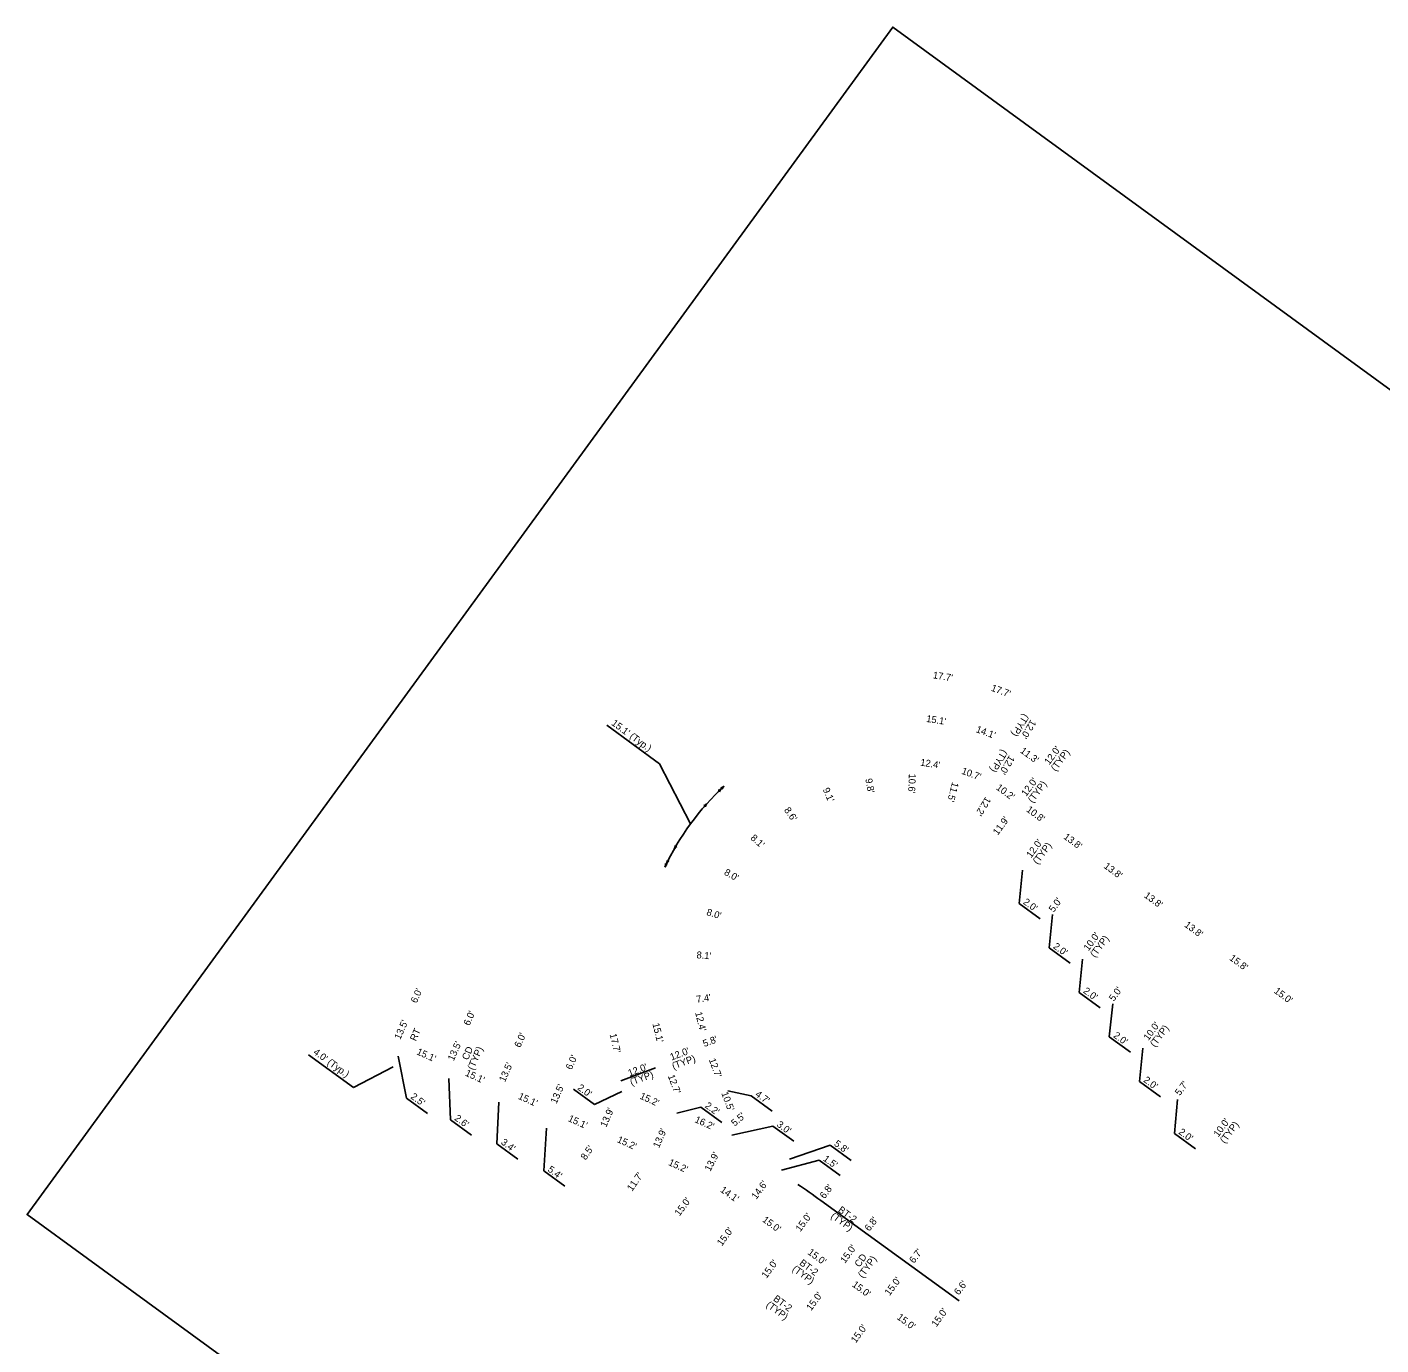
# Model space of a CAD drawing. Extents: x 15567221 to 15568484, y 8782768 to 8783889.
# Drawn here: x 15567746.9 to 15568115.4, y 8783249.6 to 8783608.3 of the extents above; entities that cross this region are included whole.
import ezdxf

# ---------------------------------------------------------------- set-up
doc = ezdxf.new("R2010")
doc.units = 0
for name, color, linetype in [('Drainage', 7, 'Continuous'), ('EXT_C', 7, 'Continuous'), ('EXT_GU', 7, 'Continuous'), ('NamedBoundary', 7, 'Continuous'), ('SheetText', 7, 'Continuous')]:
    doc.layers.add(name, color=color, linetype=linetype)

msp = doc.modelspace()

# ---------------------------------------------------------------- linework, layer by layer
at = {"layer": 'Drainage'}
for p, q in [((15567904.72, 8783418.28), (15567919.08, 8783407.82)), ((15567927.51, 8783391.49), (15567919.08, 8783407.82)), ((15568017.87, 8783378.83), (15568016.94, 8783369.8)), ((15568022.66, 8783365.63), (15568016.94, 8783369.8)), ((15568026.05, 8783366.75), (15568025.13, 8783357.72)), ((15568030.85, 8783353.55), (15568025.13, 8783357.72)), ((15568034.24, 8783354.63), (15568033.32, 8783345.6)), ((15568039.04, 8783341.43), (15568033.32, 8783345.6)), ((15568042.43, 8783342.5), (15568041.51, 8783333.47)), ((15568047.23, 8783329.3), (15568041.51, 8783333.47)), ((15567835.75, 8783319.69), (15567823.53, 8783328.6)), ((15567847.89, 8783328.25), (15567850.22, 8783316.84)), ((15568050.63, 8783330.38), (15568049.7, 8783321.35)), ((15567846.6, 8783325.3), (15567835.75, 8783319.69)), ((15567861.74, 8783322.19), (15567862.16, 8783310.95)), ((15568055.42, 8783317.18), (15568049.7, 8783321.35)), ((15567855.94, 8783312.67), (15567850.22, 8783316.84)), ((15567875.29, 8783315.76), (15567874.81, 8783304.41)), ((15567901.36, 8783315.08), (15567895.64, 8783319.25)), ((15567908.77, 8783318.63), (15567901.36, 8783315.08)), ((15567937.63, 8783318.81), (15567944.03, 8783317.46)), ((15567949.75, 8783313.29), (15567944.03, 8783317.46)), ((15568060.03, 8783316.46), (15568059.26, 8783307.21)), ((15567923.82, 8783312.76), (15567930.33, 8783314.37)), ((15567936.05, 8783310.2), (15567930.33, 8783314.37)), ((15567867.88, 8783306.78), (15567862.16, 8783310.95)), ((15567888.33, 8783308.65), (15567887.54, 8783297)), ((15567938.72, 8783306.75), (15567949.87, 8783309.23)), ((15567955.59, 8783305.06), (15567949.87, 8783309.23)), ((15568064.98, 8783303.04), (15568059.26, 8783307.21)), ((15567880.53, 8783300.24), (15567874.81, 8783304.41)), ((15567954.49, 8783300.18), (15567965.48, 8783304)), ((15567971.2, 8783299.83), (15567965.48, 8783304)), ((15567952.31, 8783297.18), (15567962.51, 8783299.91)), ((15567968.23, 8783295.74), (15567962.51, 8783299.91)), ((15567893.26, 8783292.83), (15567887.54, 8783297))]:
    msp.add_line(p, q, dxfattribs=at)
msp.add_arc((15567984.43, 8783349.93), 70.47, 132.6629, 155.0691, dxfattribs=at)
at = {"layer": 'EXT_C'}
msp.add_line((15567908.58, 8783321.51), (15567917.94, 8783325.02), dxfattribs=at)
at = {"layer": 'EXT_GU'}
for p, q in [((15567935.97, 8783401.1), (15567935.28, 8783400.43)), ((15567935.97, 8783401.1), (15567935.62, 8783400.76)), ((15567936.67, 8783401.75), (15567935.97, 8783401.1)), ((15567936.67, 8783401.75), (15567936.32, 8783401.42)), ((15567932.02, 8783397.04), (15567931.38, 8783396.33)), ((15567932.02, 8783397.04), (15567931.7, 8783396.68)), ((15567923.07, 8783384.59), (15567923.55, 8783385.42)), ((15567923.07, 8783384.59), (15567923.31, 8783385.01)), ((15567920.53, 8783379.64), (15567920.94, 8783380.51)), ((15567920.53, 8783379.64), (15567920.73, 8783380.08)), ((15567920.94, 8783380.51), (15567921.36, 8783381.37)), ((15567920.94, 8783380.51), (15567921.15, 8783380.94))]:
    msp.add_line(p, q, dxfattribs=at)
for centre, radius, start, end in [((15567934.5, 8783402.63), 2.12, 285.7627, 313.8352), ((15567934.68, 8783399.86), 0.821, 26.1019, 61.5686), ((15567937.44, 8783399.56), 2.12, 133.8352, 161.9077), ((15567935.22, 8783403.3), 2.12, 284.9814, 313.0539), ((15567935.37, 8783400.54), 0.821, 25.3205, 60.7872), ((15567938.12, 8783400.2), 2.12, 133.0539, 161.1263), ((15567930.43, 8783398.45), 2.12, 290.3631, 318.4356), ((15567933.61, 8783395.63), 2.12, 138.4356, 166.5081), ((15567930.84, 8783395.71), 0.821, 30.7022, 66.1689), ((15567921.22, 8783385.64), 2.12, 330.1539, 358.2264), ((15567924.91, 8783383.53), 2.12, 122.0814, 150.1539), ((15567923.95, 8783386.13), 0.821, 222.4206, 257.8873), ((15567918.6, 8783380.55), 2.12, 334.6787, 2.7512), ((15567922.45, 8783378.73), 2.12, 126.6062, 154.6787), ((15567921.29, 8783381.25), 0.821, 226.9453, 262.412), ((15567919.03, 8783381.44), 2.12, 333.8973, 1.9698), ((15567922.84, 8783379.57), 2.12, 125.8248, 153.8973), ((15567921.72, 8783382.11), 0.821, 226.164, 261.6307)]:
    msp.add_arc(centre, radius, start, end, dxfattribs=at)
at = {"layer": 'NamedBoundary'}
msp.add_lwpolyline([(15568248.32, 8782919.55), (15568483.96, 8783242.77), (15567982.56, 8783608.32), (15567746.92, 8783285.1)], close=True, dxfattribs=at)
at = {"layer": 'SheetText'}
msp.add_line((15568000.65, 8783261.64), (15567962.96, 8783288.97), dxfattribs=at)
msp.add_arc((15567845.54, 8783127.07), 200, 54.0482, 56.24, dxfattribs=at)

# ---------------------------------------------------------------- texts
at = {"layer": 'Drainage'}
for s, height, rotation, p in [("17.7'", 1.89, 351.25, (15567993.4, 8783431.08)), ("17.7'", 1.89, 339.9202, (15568009.17, 8783427.73)), ("15.1' (Typ.)", 1.8898, 323.7364, (15567905.82, 8783418.52)), ("15.1'", 1.89, 351.25, (15567991.58, 8783419.22)), ('(TYP)', 1.89, 238.7193, (15568018.21, 8783421.57)), ("12.0'", 1.89, 238.7193, (15568020.15, 8783419.97)), ("14.1'", 1.89, 339.9202, (15568005.05, 8783416.47)), ('(TYP)', 1.89, 238.7193, (15568012.37, 8783411.84)), ("11.3'", 1.89, 323.584, (15568017.08, 8783411.02)), ("12.0'", 1.89, 53.4236, (15568025.15, 8783407.39)), ('(TYP)', 1.89, 53.4236, (15568026.93, 8783405.61)), ("12.4'", 1.89, 351.0495, (15567989.95, 8783407.34)), ("12.0'", 1.89, 238.7193, (15568014.31, 8783410.24)), ("10.6'", 1.89, 268.0457, (15567986.95, 8783405.18)), ("10.7'", 1.89, 339.7197, (15568001.12, 8783405.14)), ("12.0'", 1.89, 53.4236, (15568018.88, 8783398.79)), ("9.1'", 1.89, 293.0451, (15567963.46, 8783400.85)), ("9.8'", 1.89, 280.5454, (15567975.07, 8783403.66)), ("11.5'", 1.89, 255.5459, (15567998.75, 8783402.95)), ("10.2'", 1.89, 323.584, (15568010.53, 8783400.98)), ('(TYP)', 1.89, 53.4236, (15568020.66, 8783397.01)), ("12.2'", 1.89, 238.7193, (15568007.84, 8783398.98)), ("8.6'", 1.89, 305.5449, (15567952.87, 8783395.19)), ("11.9'", 1.89, 53.4236, (15568011.14, 8783388.23)), ("10.8'", 1.89, 323.584, (15568018.75, 8783394.99)), ("8.1'", 1.89, 318.0446, (15567943.69, 8783387.41)), ("12.0'", 1.89, 53.4236, (15568020.23, 8783382.04)), ('(TYP)', 1.89, 53.4236, (15568022.01, 8783380.27)), ("13.8'", 1.89, 323.584, (15568028.88, 8783387.6)), ("8.0'", 1.89, 330.5444, (15567936.48, 8783377.74)), ("13.8'", 1.89, 323.584, (15568039.85, 8783379.61)), ("2.0'", 1.89, 323.7364, (15568017.88, 8783369.85)), ("5.0'", 1.89, 53.4236, (15568026.35, 8783367.26)), ("13.8'", 1.89, 323.584, (15568050.81, 8783371.62)), ("8.0'", 1.89, 343.0441, (15567931.71, 8783366.67)), ("13.8'", 1.89, 323.584, (15568061.78, 8783363.62)), ("10.0'", 1.89, 53.4236, (15568035.83, 8783356.72)), ('(TYP)', 1.89, 53.4236, (15568037.61, 8783354.94)), ("8.1'", 1.89, 355.5438, (15567929.09, 8783354.89)), ("2.0'", 1.89, 323.7364, (15568026.06, 8783357.77)), ("15.8'", 1.89, 323.584, (15568074.03, 8783354.58)), ("6.0'", 1.89, 65.9905, (15567852.95, 8783342.5)), ("7.4'", 1.89, 8.0436, (15567929.21, 8783342.77)), ("2.0'", 1.89, 323.7364, (15568034.25, 8783345.64)), ("5.0'", 1.89, 53.4236, (15568042.73, 8783343.02)), ("15.0'", 1.89, 323.584, (15568086.18, 8783345.62)), ("13.5'", 1.89, 65.9905, (15567848.49, 8783332.6)), ("6.0'", 1.89, 65.9905, (15567867.32, 8783336.39)), ("12.4'", 1.89, 283.5471, (15567928.75, 8783340.09)), ('RT', 1.89, 65.9905, (15567852.75, 8783332.18)), ("6.0'", 1.89, 65.9905, (15567881.15, 8783330.41)), ("17.7'", 1.89, 283.7477, (15567905.47, 8783334.19)), ("15.1'", 1.89, 283.7477, (15567917.13, 8783337.04)), ("2.0'", 1.89, 323.7364, (15568042.44, 8783333.52)), ("10.0'", 1.89, 53.4236, (15568052.14, 8783332.34)), ('(TYP)', 1.89, 53.4236, (15568053.92, 8783330.56)), ("13.5'", 1.89, 65.9905, (15567863.04, 8783326.8)), ('CD', 1.89, 65.9905, (15567866.9, 8783327.01)), ('(TYP)', 1.89, 65.9905, (15567868.41, 8783324.3)), ("12.0'", 1.89, 20.5433, (15567922.34, 8783327.04)), ("5.8'", 1.89, 20.5433, (15567931.28, 8783330.7)), ("4.0' (Typ.)", 1.8898, 323.9055, (15567824.66, 8783328.97)), ("15.1'", 1.89, 335.7021, (15567852.78, 8783328.8)), ("6.0'", 1.89, 65.9905, (15567895.14, 8783324.37)), ('(TYP)', 1.89, 20.5433, (15567922.88, 8783324.58)), ("12.7'", 1.89, 290.5433, (15567932.45, 8783327.27)), ("15.1'", 1.89, 335.7021, (15567866.01, 8783322.99)), ("13.5'", 1.89, 65.9905, (15567876.99, 8783321.05)), ("12.0'", 1.89, 20.5433, (15567910.9, 8783322.68)), ('(TYP)', 1.89, 20.5433, (15567911.43, 8783320.22)), ("12.7'", 1.89, 290.5433, (15567921.29, 8783322.84)), ("13.5'", 1.89, 65.9905, (15567891.02, 8783315.14)), ("2.0'", 1.89, 323.7364, (15567896.57, 8783319.3)), ("2.0'", 1.89, 323.7364, (15568050.63, 8783321.4)), ("5.7'", 1.89, 53.4236, (15568060.7, 8783317.34)), ("2.5'", 1.89, 323.7364, (15567851.16, 8783316.89)), ("15.1'", 1.89, 335.7021, (15567880.43, 8783316.68)), ("15.2'", 1.89, 335.7021, (15567913.53, 8783316.73)), ("10.5'", 1.89, 290.5433, (15567935.86, 8783318.16)), ("4.7'", 1.89, 323.7364, (15567944.96, 8783317.51)), ("2.6'", 1.89, 323.7364, (15567863.09, 8783311)), ("15.1'", 1.89, 335.7021, (15567894.01, 8783310.63)), ("13.9'", 1.89, 65.9905, (15567904.54, 8783308.74)), ("2.2'", 1.89, 323.7364, (15567931.27, 8783314.41)), ("5.5'", 1.89, 40.5433, (15567939.55, 8783309.03)), ("13.9'", 1.89, 65.9905, (15567918.9, 8783303.09)), ("16.2'", 1.89, 335.7021, (15567928.49, 8783310.33)), ("3.0'", 1.89, 323.7364, (15567950.81, 8783309.28)), ("2.0'", 1.89, 323.7364, (15568060.19, 8783307.25)), ("10.0'", 1.89, 53.4236, (15568071.18, 8783306.09)), ('(TYP)', 1.89, 53.4236, (15568072.96, 8783304.32)), ("3.4'", 1.89, 323.7364, (15567875.74, 8783304.46)), ("15.2'", 1.89, 335.7021, (15567907.36, 8783304.89)), ("5.8'", 1.89, 323.7364, (15567966.42, 8783304.05)), ("8.5'", 1.89, 55.2678, (15567898.98, 8783299.81)), ("13.9'", 1.89, 62.4357, (15567932.88, 8783296.73)), ("1.5'", 1.89, 323.7364, (15567963.44, 8783299.96)), ("5.4'", 1.89, 323.7364, (15567888.47, 8783297.05)), ("15.2'", 1.89, 335.7021, (15567921.32, 8783298.66)), ("11.7'", 1.89, 55.2678, (15567911.61, 8783291.32)), ("14.6'", 1.89, 53.584, (15567945.42, 8783289.12)), ("15.0'", 1.89, 53.584, (15567924.52, 8783284.56)), ("14.1'", 1.89, 325.0513, (15567935.44, 8783291.46)), ("6.8'", 1.89, 52.6798, (15567963.99, 8783289.28)), ('BT-2', 1.89, 323.584, (15567967.49, 8783286.04)), ("15.0'", 1.89, 323.584, (15567946.9, 8783283.37)), ("15.0'", 1.89, 53.584, (15567957.4, 8783280.31)), ('(TYP)', 1.89, 323.584, (15567965.53, 8783284.39)), ("6.8'", 1.89, 52.6798, (15567976.21, 8783280.42)), ("15.0'", 1.89, 53.584, (15567936.05, 8783276.42)), ("15.0'", 1.89, 323.584, (15567959.24, 8783274.49)), ("15.0'", 1.89, 53.584, (15567969.56, 8783271.71)), ("6.7'", 1.89, 52.6798, (15567988.34, 8783271.7)), ("15.0'", 1.89, 53.584, (15567948.19, 8783267.61)), ('BT-2', 1.89, 323.584, (15567956.98, 8783271.62)), ('CD', 1.89, 54.748, (15567973.51, 8783270.64)), ('(TYP)', 1.89, 54.748, (15567974.47, 8783267.68)), ('(TYP)', 1.89, 323.584, (15567955.02, 8783269.97)), ("15.0'", 1.89, 53.584, (15567981.71, 8783262.9)), ("15.0'", 1.89, 53.584, (15567960.34, 8783258.81)), ("15.0'", 1.89, 323.584, (15567971.32, 8783265.72)), ("6.6'", 1.89, 52.6798, (15568000.53, 8783263.06)), ('(TYP)', 1.89, 323.584, (15567947.91, 8783260.22)), ('BT-2', 1.89, 323.584, (15567949.87, 8783261.87)), ("15.0'", 1.89, 323.584, (15567983.53, 8783256.82)), ("15.0'", 1.89, 54.3971, (15567994.45, 8783254.39)), ("15.0'", 1.89, 53.584, (15567972.48, 8783250))]:
    msp.add_text(s, height=height, rotation=rotation, dxfattribs=at).set_placement(p)

doc.saveas('drawing.dxf')
